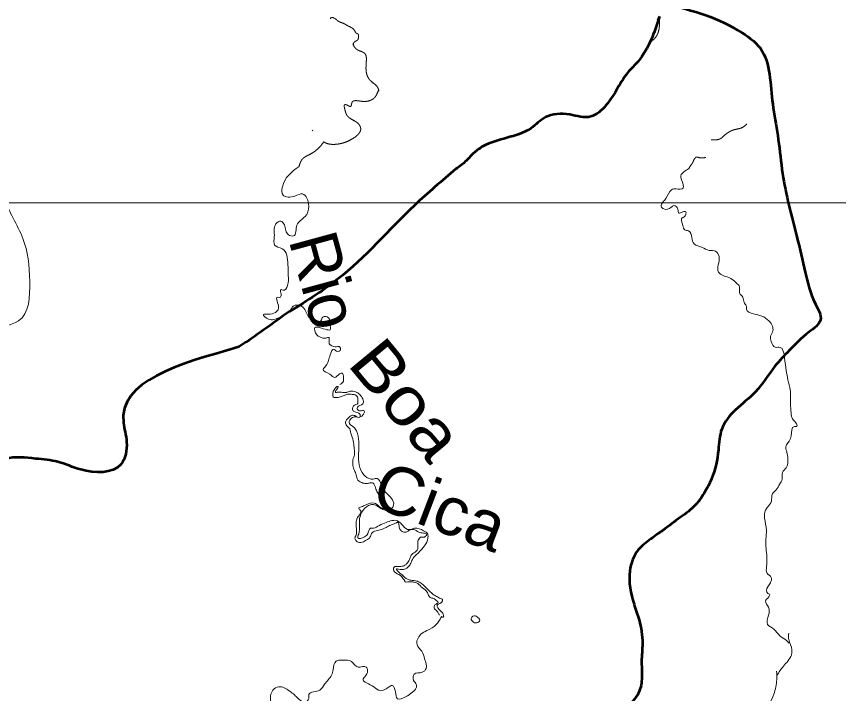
# Model space of a CAD drawing. Extents: x 512883 to 1063249, y 8784064 to 9081064.
# Drawn here: x 748785 to 774412, y 8877293 to 8898395 of the extents above; entities that cross this region are included whole.
import ezdxf

# ---------------------------------------------------------------- set-up
doc = ezdxf.new("R2010")
doc.units = 0
doc.header["$LTSCALE"] = 600
doc.linetypes.add('DOT_DASHED', pattern=[7.7, 5, -1.2, 0.3, -1.2])
for name, color, linetype, lineweight in [('1', 7, 'Continuous', 25), ('10', 7, 'Continuous', 53), ('4', 7, 'Continuous', 13), ('9', 7, 'Continuous', 70)]:
    doc.layers.add(name, color=color, linetype=linetype, lineweight=lineweight)
doc.layers.add('14', color=7, linetype='Continuous')

msp = doc.modelspace()

# ---------------------------------------------------------------- linework, layer by layer
at = {"layer": '1', "lineweight": 13}
msp.add_line((581090.6, 8892594.3), (934660.9, 8892579.8), dxfattribs=at)
at = {"layer": '10'}
msp.add_line((768831.1, 8898395.2), (768781.1, 8898268.6), dxfattribs=at)
for points in [[(768998.4, 8898787.4), (770271.4, 8898437.3), (771402.6, 8897887.1), (772033.9, 8897316.5), (772270.7, 8896481), (772375.9, 8895543.6), (772533.7, 8894565.4), (772665.2, 8893505.8), (773112.4, 8891529), (773375.5, 8890428.6), (773691.1, 8889430.1), (773849, 8888941), (773480.7, 8888553.8), (772875.7, 8887983.2), (772428.5, 8887494.1), (771823.5, 8886699.3), (771192.1, 8886128.8), (770771.2, 8885537.8), (770666, 8884885.7), (770455.6, 8883989), (770218.8, 8883540.7), (769955.8, 8883173.9), (769482.3, 8882786.7), (768929.9, 8882379.1), (768561.6, 8882114.2), (768167, 8881767.8), (767904, 8881115.7), (768035.5, 8880076.3), (768193.3, 8879587.3), (768298.5, 8878853.6), (768272.2, 8878283.1), (768272.2, 8877671.7), (768140.7, 8877243.8), (767693.5, 8876795.4), (767298.9, 8876428.6), (766036.3, 8875124.4), (765878.4, 8874451.9), (765773.2, 8874023.9), (765746.9, 8873269.9), (765589.1, 8872373.3), (765141.9, 8871456.3), (765326, 8870743), (765957.4, 8869927.9), (767173.9, 8867660)], [(768831.1, 8898395.2), (768162.8, 8896996.2), (767837.2, 8896640.4), (767480.9, 8896086.4), (767150.1, 8895613.7), (766692.1, 8895273.2), (766030.5, 8895334.2), (765272.3, 8895252.9), (764814.2, 8894907.2), (764071.2, 8894612.4), (763333.3, 8894348.2), (763058.5, 8894155), (762804.1, 8893895.8), (762483.5, 8893641.7)], [(762483.5, 8893641.7), (761195.1, 8892507.8), (758797.5, 8890203.4), (757198.2, 8889136.4)], [(757198.2, 8889136.4), (755746, 8888119.4), (755690.2, 8888084)], [(755690.2, 8888084), (752119.9, 8885734.8), (752219, 8885133.7), (752040.6, 8884432.4), (750792.3, 8884272.1), (750079, 8884512.5), (749385.4, 8884612.7), (748454.1, 8884592.7), (747879.5, 8884211.9), (746651, 8883370.3), (746016.9, 8882528.7), (745382.8, 8881446.7), (744867.7, 8880645.1)]]:
    msp.add_spline(points, degree=3, dxfattribs=at)
at = {"layer": '4', "linetype": 'DOT_DASHED'}
msp.add_line((758022.3, 8894834.1), (758000, 8894851.3), dxfattribs=at)
at = {"layer": '4'}
msp.add_line((762956.5, 8879602.1), (762956.5, 8879591.9), dxfattribs=at)
msp.add_line((762956.5, 8879602.1), (762956.5, 8879591.9), dxfattribs=at)
for points in [[(810054.4, 8878245.8), (808490.8, 8878441.8), (807059.7, 8878479.1), (805985.9, 8879079.1), (805197, 8879388.8), (804089.5, 8879302.2), (802915.8, 8879818.7), (802471.2, 8879942.2), (801566.7, 8879710.6), (800194.7, 8879893.7), (799198.8, 8880764.4), (798539.4, 8882281), (798171.6, 8882800), (797688, 8882798.5), (797359, 8883484), (796899, 8885209.2), (796928.8, 8886291.1), (797076.8, 8887664.5), (796864.6, 8888766.4), (796120.9, 8890657.2), (796158, 8890990.2), (795488.6, 8891445.8), (794233.1, 8892086.9), (793990.2, 8892190.2), (793056.1, 8892936.3), (792600.3, 8894224.7), (792515.5, 8894661.3), (792310, 8895076.7), (792346.1, 8895513.7), (792422, 8895992.4), (792272.6, 8896865.6), (792611.1, 8897282.7), (793187.8, 8898075), (792840.8, 8898531.6), (792656.5, 8898843.1), (792469.9, 8899383.4), (792192.5, 8900984.4), (791233.7, 8902188), (791205.1, 8903061.7), (790428.6, 8904182.7), (790301.6, 8904806.3), (790202.7, 8906699.1), (789491.8, 8907279.4), (788677.8, 8908109.1), (788165.6, 8908981.2), (787558.3, 8909270.7), (786890.9, 8909518.3), (786443.6, 8909933), (785940.4, 8909869), (785293, 8910137.5), (784748.1, 8910219.1), (784086.8, 8909842.6), (783816.4, 8910715.5), (784068.9, 8911694), (784280.1, 8912776.4), (784271, 8913712.5), (783654.5, 8914958.8), (782986.1, 8915310.4), (782138.8, 8915411.9), (781433.7, 8915388.9), (780682.1, 8916010.8), (780211, 8916799.8), (779683.5, 8917172.7), (779000.8, 8916921), (778497.4, 8916877.9), (777545.7, 8917353.4), (776860.6, 8917351.4), (776253.1, 8917661.6), (776325.9, 8918473.1), (776421.2, 8919035.1), (776035.5, 8919325.1), (775038.5, 8920320.7), (774913.4, 8920757.1), (774003.6, 8921066.4), (773776.3, 8921648.2), (773369.1, 8922083.8), (772780.5, 8922518.9), (772330.2, 8923245.7), (771656.7, 8924117.3), (770865.2, 8924697.4), (769915.8, 8924944.2), (769007.4, 8925107.8), (768078.7, 8925292.3), (767367.8, 8925872.6), (766592, 8926910.4), (766120.9, 8927699.5), (765223, 8928861.7), (764733, 8929525.9), (764526.3, 8930066.2), (764442.5, 8930398.7), (763934.9, 8930792.5)], [(744501.9, 8869598.5), (744470, 8870556.5), (743738.4, 8872229.9), (744063.6, 8873152.6), (743349.9, 8874434.9), (743618.1, 8875934.2), (744918.6, 8879583.7), (745542.8, 8880277.2), (747016.9, 8882711.3), (748172.5, 8885457), (748475.8, 8886030.2), (748062.7, 8887371.4), (748049, 8888564.8), (748851.5, 8888906.8), (749198.3, 8890137.9), (748985.3, 8891477.2), (748411.7, 8892758.2), (748220.9, 8894508.7), (747785.8, 8895479.8), (747431.7, 8896635.3), (745359.3, 8898362.7), (743270.6, 8900769.2), (742255.5, 8901828.1), (741455.1, 8901876.9), (740658, 8902542.9), (740040, 8903001.4)], [(757592.9, 8893717.9), (757074.2, 8893087.4), (757094.6, 8892828.2), (757462.9, 8892797.7), (757703.3, 8892863.8), (757897.7, 8892482.7), (757780.1, 8892157.5), (757529.4, 8891893.3), (757422, 8891552.9), (757263.4, 8891588.4), (757135.6, 8891903.5), (757023, 8892015.2), (756874.7, 8891928.9), (756823.5, 8891522.4), (756833.8, 8891268.3), (757063.9, 8891156.5), (757248.1, 8890668.8), (757258.3, 8890318.2), (757237.8, 8890008.2), (757089.5, 8889860.9), (757033.2, 8889886.3), (757012.8, 8889642.4), (756925.8, 8889642.4), (756956.5, 8889317.2), (756808.2, 8889144.4), (756562.7, 8889119), (756485.9, 8889108.8), (756644.5, 8888961.5), (756803.1, 8888946.3), (757110, 8889078.4), (757314.6, 8889225.7), (757411.8, 8889362.9), (757672.6, 8889368), (757882.3, 8889053), (758035.8, 8888931), (758276.2, 8888910.7), (758337.6, 8889027.6), (758511.5, 8889007.2), (758552.4, 8888788.7), (758578, 8888651.6), (758235.3, 8888697.3), (758087, 8888697.3), (758148.3, 8888473.7), (758337.6, 8888372.1), (758429.7, 8888367), (758521.7, 8888392.4), (758532, 8888260.3), (758537.1, 8888194.2), (758721.2, 8888102.8), (758762.2, 8888102.8), (758844, 8888113), (758874.7, 8887985.9), (758726.3, 8887985.9), (758690.5, 8888016.4), (758537.1, 8887752.2), (758419.4, 8887493.1), (758342.7, 8887396.5), (758557.5, 8887244.1), (758705.9, 8887142.5), (758854.2, 8887254.2), (758946.3, 8887274.6), (758977, 8887142.5), (758977, 8887025.6), (758869.6, 8886929.1)], [(769745.6, 8893651.8), (769498.7, 8893432.9), (769565.2, 8893158.5), (769565.2, 8893046.7), (769350.4, 8893021.3), (769207.2, 8892995.9), (769028.1, 8892716.4), (768931, 8892604.7), (768879.8, 8892477.6), (768961.6, 8892396.3), (769191.8, 8892447.1), (769283.9, 8892503), (769401.5, 8892391.2), (769432.2, 8892264.2), (769560.1, 8892304.9), (769647.1, 8892304.9), (769595.9, 8892147.3), (769539.6, 8892121.9), (769560.1, 8891883.1), (769616.4, 8891740.9), (769734, 8891715.5), (769836.3, 8891502.1), (769907.9, 8891309), (770158.6, 8891197.2), (770378.5, 8891105.7), (770578, 8891075.2), (770685.4, 8890917.7), (770659.8, 8890653.5), (770670.1, 8890424.9), (770813.3, 8890318.2), (771048.6, 8890231.8), (771232.7, 8890084.4), (771324.8, 8889962.5), (771324.8, 8889779.6), (771427.1, 8889642.4), (771468, 8889484.8), (771534.5, 8889378.2), (771539.6, 8889276.5), (771759.6, 8889124.1), (772020.5, 8889058), (772240.4, 8888905.6), (772352.9, 8888737.9), (772363.2, 8888600.7), (772291.6, 8888433.1), (772312, 8888265.4), (772439.9, 8888087.6), (772588.2, 8888082.5), (772726.3, 8887762.4), (772782.6, 8887360.9), (772833.8, 8887071.3), (772905.4, 8886756.3), (772910.5, 8886319.3), (772931, 8886044.9), (772971.9, 8885851.9), (773079.3, 8885735), (773110, 8885618.1), (773038.4, 8885618.1), (772936.1, 8885328.5), (772869.6, 8885160.8), (772792.8, 8885044), (772767.3, 8884988.1), (772798, 8884820.4), (772828.6, 8884601.9), (772782.6, 8884332.6), (772659.8, 8884180.2), (772654.7, 8883971.9), (772578, 8883824.5), (772465.5, 8883641.6), (772347.8, 8883519.6), (772317.1, 8883285.9), (772209.7, 8883113.2), (772138.1, 8883006.4), (772107.4, 8882757.5), (772163.7, 8882381.5), (772148.3, 8882112.2), (772153.5, 8881817.5), (772168.8, 8881248.4), (772179, 8881050.2), (772312, 8880913), (772286.5, 8880745.4), (772204.6, 8880618.3), (772204.6, 8880415.1), (772260.9, 8880389.7), (772235.3, 8880308.4), (772133, 8880171.2), (772230.2, 8879983.2), (772230.2, 8879739.3), (772199.5, 8879444.6), (772393.9, 8879302.3), (772583.1, 8879088.9), (772792.8, 8878946.7), (772869.6, 8878865.3)], [(758741.7, 8886827.4), (758675.2, 8886741.1), (758644.5, 8886619.1), (758659.8, 8886537.8), (758731.5, 8886517.5), (758884.9, 8886537.8), (758997.4, 8886583.6), (759104.9, 8886619.1), (759217.4, 8886619.1), (759345.3, 8886598.8), (759427.1, 8886497.2), (759427.1, 8886410.8), (759427.1, 8886329.5), (759289, 8886263.4), (759268.5, 8886207.5), (759258.3, 8886161.8), (759304.3, 8886085.6), (759437.3, 8886044.9), (759503.8, 8885968.7), (759488.5, 8885902.7), (759329.9, 8885953.5), (759237.8, 8885963.7), (759120.2, 8885872.2), (759063.9, 8885806.1), (759043.5, 8885750.2), (759084.4, 8885638.5), (759191.8, 8885501.3), (759207.2, 8885404.7), (759253.2, 8885282.8), (759299.2, 8885054.1), (759319.7, 8884876.3), (759319.7, 8884734), (759273.7, 8884576.5), (759268.5, 8884480), (759294.1, 8884317.4), (759350.4, 8884180.2), (759396.4, 8884022.7), (759427.1, 8883946.4), (759468, 8883910.9), (759585.7, 8883855), (759703.3, 8883839.8), (759805.6, 8883860.1), (759882.3, 8883860.1), (759928.4, 8883824.5), (759989.8, 8883661.9), (760056.3, 8883529.8), (760122.8, 8883402.8), (760204.6, 8883321.5), (760291.6, 8883209.7), (760342.7, 8883092.8), (760347.8, 8883062.3), (760148.3, 8883087.8), (760010.2, 8883199), (759936.9, 8883229.6), (759631.7, 8883153.8), (759493.6, 8883092.8), (759452.7, 8883067.4), (759503.8, 8883011.5), (759514.1, 8882920.1), (759452.7, 8882833.7), (759391.3, 8882727), (759376, 8882589.8), (759381.1, 8882447.5), (759381.1, 8882269.7), (759340.2, 8882152.8), (759340.2, 8882102), (759401.5, 8882025.8), (759565.2, 8882010.6), (759703.3, 8882081.7), (759805.6, 8882163), (759851.7, 8882284.9), (759948.8, 8882351), (760127.9, 8882391.6), (760306.9, 8882472.9), (760455.2, 8882544.1), (760532, 8882574.6), (760629.2, 8882615.2), (760649.6, 8882625.4), (760675.2, 8882630.4), (760700.8, 8882589.8), (760726.3, 8882447.5), (760762.2, 8882381.5), (760859.3, 8882325.6), (760956.5, 8882330.7), (761038.4, 8882386.6), (761161.1, 8882406.9), (761324.8, 8882325.6), (761478.3, 8882295.1), (761570.3, 8882254.4), (761539.6, 8882193.5), (761376, 8882168.1)], [(762107.4, 8879688.5), (762087, 8879769.8), (762000, 8879871.4), (761897.7, 8880044.2), (762066.5, 8880181.4), (762066.5, 8880222), (762030.7, 8880242.3), (761913, 8880303.3), (761790.3, 8880374.4), (761345.3, 8880765.7), (761222.5, 8880806.3), (761120.2, 8880816.5), (760977, 8880857.1), (760808.2, 8880989.2), (760629.2, 8881182.3), (760792.8, 8881156.9), (760997.4, 8881238.2), (761079.3, 8881355.1), (761150.9, 8881512.6), (761268.5, 8881634.6), (761376, 8881746.3), (761616.4, 8882203.6), (761606.1, 8882259.5), (761478.3, 8882366.2), (761196.9, 8882447.5), (761023, 8882401.8), (760659.8, 8882676.2), (760312, 8882625.4), (760097.2, 8882533.9), (759913, 8882447.5), (759826.1, 8882442.4), (759734, 8882269.7), (759636.8, 8882173.2), (759427.1, 8882142.7), (759452.7, 8882264.6), (759483.4, 8882747.3), (759821, 8883174.1), (759948.8, 8883174.1), (760081.8, 8883097.9), (760209.7, 8883031.8), (760342.7, 8883001.4), (760470.6, 8883052.2), (760542.2, 8883169), (760480.8, 8883372.3), (760281.3, 8883575.5), (760173.9, 8883804.2), (760092.1, 8883941.4), (760030.7, 8883992.2), (759907.9, 8883976.9), (759774.9, 8883997.3), (759560.1, 8884180.2), (759340.2, 8885547), (759258.3, 8885628.3), (759166.2, 8885704.5), (759161.1, 8885775.7), (759263.4, 8885897.6), (759370.8, 8885917.9), (759483.4, 8885902.7), (759626.6, 8886105.9), (759483.4, 8886105.9), (759416.9, 8886141.5), (759411.8, 8886217.7), (759580.6, 8886324.4), (759595.9, 8886431.1), (759514.1, 8886583.6), (759391.3, 8886680.1), (759222.5, 8886720.7), (759089.5, 8886685.2), (759079.3, 8886680.1), (758946.3, 8886680.1), (758813.3, 8886685.2), (758726.3, 8886685.2), (758757, 8886756.3), (758803.1, 8886822.4), (758818.4, 8886857.9)], [(758741.7, 8886827.4), (758767.3, 8886857.9), (758818.4, 8886857.9)], [(761376, 8882168.1), (761345.3, 8882132.5), (761309.5, 8882071.5), (761294.1, 8881954.7), (761294.1, 8881807.3), (761243, 8881726), (761115.1, 8881634.6), (761048.6, 8881502.4), (760977, 8881370.3), (760910.5, 8881304.3), (760813.3, 8881258.6), (760726.3, 8881248.4), (760654.7, 8881253.5), (760578, 8881248.4), (760542.2, 8881202.7), (760567.8, 8881090.9), (760751.9, 8880974), (760844, 8880872.4), (760890, 8880806.3), (760905.4, 8880770.8), (760982.1, 8880770.8), (761130.4, 8880770.8), (761258.3, 8880745.4), (761401.5, 8880623.4), (761560.1, 8880491.3), (761621.5, 8880379.5), (761682.9, 8880288.1), (761795.4, 8880257.6), (761887.5, 8880181.4), (761928.4, 8880135.6), (761892.6, 8880095), (761815.9, 8880039.1), (761805.6, 8879962.9), (761902.8, 8879851.1), (761954, 8879769.8), (761969.3, 8879739.3)], [(756792.8, 8875898), (756792.8, 8876162.2), (756654.7, 8876360.4), (756659.8, 8876665.2), (756700.8, 8876939.6), (756700.8, 8877142.9), (756777.5, 8877396.9), (756961.6, 8877503.6), (757283.9, 8877381.7), (757539.6, 8877168.3), (757749.4, 8877036.2), (757882.3, 8877097.1), (757902.8, 8877259.7), (758240.4, 8877402), (758388.8, 8877584.9), (758608.7, 8877864.4), (758654.7, 8878042.2), (758746.8, 8878301.3), (758951.4, 8878331.8), (759227.6, 8878291.2), (759437.3, 8878118.4), (759688, 8878118.4), (759723.8, 8878057.5), (759672.6, 8877854.2), (759590.8, 8877717), (759693.1, 8877625.6), (759923.3, 8877498.5), (760127.9, 8877381.7), (760373.4, 8877483.3), (760496.2, 8877544.3), (760598.5, 8877351.2), (760665, 8877132.7), (760915.6, 8877193.7), (761115.1, 8877325.8), (761243, 8877468.1), (761248.1, 8877579.8), (761166.2, 8877696.7), (761186.7, 8877899.9), (761432.2, 8877955.8), (761560.1, 8878077.8), (761509, 8878372.5), (761422, 8878611.3), (761273.7, 8878809.5), (761324.8, 8879063.5), (761672.6, 8879302.3), (761913, 8879490.3), (761989.8, 8879612.3), (762046, 8879703.7)], [(762026.5, 8879672), (762081.8, 8879678.3), (762107.4, 8879688.5)], [(762956.5, 8879591.9), (762977, 8879673.2), (763048.6, 8879713.9), (763181.6, 8879658), (763232.7, 8879571.6), (763140.7, 8879500.5), (763063.9, 8879500.5), (762997.4, 8879546.2), (762956.5, 8879602.1)], [(762956.5, 8879591.9), (762977, 8879673.2), (763048.6, 8879713.9), (763181.6, 8879658), (763232.7, 8879571.6), (763140.7, 8879500.5), (763063.9, 8879500.5), (762997.4, 8879546.2), (762956.5, 8879602.1)], [(772488.4, 8877854.2), (772690.5, 8878143.8), (772828.6, 8878306.4), (772941.2, 8878494.4), (772915.6, 8878814.5), (772859.3, 8878977.1), (772859.3, 8879170.2)], [(772481.3, 8877985.8), (772485.9, 8877732.3), (772393.9, 8877269.9), (772240.4, 8876990.4), (772020.5, 8876822.8), (771872.1, 8876538.2), (772148.3, 8876167.3), (772168.8, 8875704.9), (771948.8, 8875171.4), (771902.8, 8875044.4), (772030.7, 8875044.4), (772250.6, 8874983.4), (772301.8, 8874724.2), (772578, 8874414.3), (772736.6, 8874170.4), (772859.3, 8873982.4), (772833.8, 8873758.8), (772782.6, 8873606.4), (772977, 8873393), (773084.4, 8873194.8), (773079.3, 8872849.3), (773140.7, 8872671.5), (773125.3, 8872453), (773268.5, 8872163.4), (773370.8, 8871894.1), (773370.8, 8871675.6), (773365.7, 8871594.3), (773493.6, 8871477.4), (773636.8, 8871284.3), (773678.1, 8871408), (773739.9, 8871531.7)]]:
    msp.add_spline(points, degree=3, dxfattribs=at)
at = {"layer": '4', "linetype": 'DOT_DASHED'}
for points in [[(759290.8, 8897508.7), (759292.6, 8897565.4), (759338.4, 8897611.2), (759430, 8897677.3), (759450.4, 8897763.7), (759440.2, 8897839.9), (759363.9, 8897885.6), (759353.7, 8897900.9), (759302.8, 8897987.3), (759165.4, 8898078.8), (759084, 8898119.4), (759007.6, 8898165.2), (758936.4, 8898195.7), (758834.6, 8898236.3), (758722.7, 8898322.7), (758585.2, 8898353.2), (758570.6, 8898316.4)], [(768831.1, 8898395.2), (768707.4, 8897743.3), (768524.2, 8897580.7)], [(759269.1, 8897538.7), (759389.3, 8897372.3), (759648.8, 8897235.1), (759689.6, 8896970.8), (759694.7, 8896635.3), (759786.3, 8896432), (760050.9, 8896172.8), (760086.7, 8896073.5)], [(760074.1, 8896108.6), (759923.7, 8895842.4), (759659, 8895745.9), (759430, 8895766.2), (759251.9, 8895725.5), (759201, 8895588.3), (759078.9, 8895639.1), (759017.8, 8895644.2), (759017.8, 8895512.1), (759094.2, 8895303.7), (759292.6, 8895156.3), (759450.4, 8895044.5), (759516.5, 8894881.8), (759369, 8894653.1)], [(771557.2, 8895049.6), (771419.8, 8894937.7), (771150.1, 8894861.5), (770982.2, 8894785.3), (770829.5, 8894668.4), (770748.1, 8894597.2), (770544.5, 8894546.4), (770437.5, 8894554.7)], [(757592.9, 8893717.9), (757699.8, 8893951.7), (757908.4, 8894083.9), (758152.7, 8894246.5), (758346.1, 8894460), (758365.7, 8894487.6)], [(759369, 8894653.1), (759155.2, 8894526.1), (758773.5, 8894414.2), (758376.6, 8894480.3), (758365.7, 8894487.6)], [(770272.6, 8894000), (770061.1, 8893997.5), (769989.8, 8894012.7), (769908.4, 8893936.5), (769852.4, 8893819.6), (769791.3, 8893733.2), (769745.6, 8893651.8)]]:
    msp.add_spline(points, degree=3, dxfattribs=at)
at = {"layer": '9'}
msp.add_spline([(739491.5, 8897319.2), (740049.1, 8897660.7), (740437.9, 8899153.6), (741034.8, 8901113.8), (743561.4, 8903764.3), (745471.9, 8905265.6), (746442.1, 8906464.9), (747159.6, 8907736.3), (749272, 8905843.1), (750962.4, 8904370)], degree=3, dxfattribs=at)

# ---------------------------------------------------------------- texts
at = {"layer": '14'}
msp.add_text('Rio', height=1500, rotation=285.269, dxfattribs=at).set_placement((757263.1, 8891430.5))
for s, rotation, width, p in [('Boa ', 309.544, 1.15, (759066.3, 8887562)), ('Cica', 339.142, 1.05, (759766.2, 8883172.6))]:
    msp.add_text(s, height=1500, rotation=rotation, dxfattribs=dict(at, width=width)).set_placement(p)

doc.saveas('drawing.dxf')
